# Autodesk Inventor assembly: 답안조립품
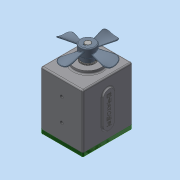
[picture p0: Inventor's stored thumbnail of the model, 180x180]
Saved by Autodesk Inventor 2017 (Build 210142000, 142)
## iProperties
Part Number: 답안조립품
Material: 일반
Document SubType Name: Assembly
Designer: MRC
Mass: 2663.33 g
Surface Area: 1952.92 cm^2
Volume: 798.897 cm^3
Density: 3.33376 g/cm^3
Author: MRC
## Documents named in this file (17)
- C:\Users\MRC\Desktop\610205V1005\답안조립품.iam
- C:\Users\MRC\Desktop\610205V1005\본체.ipt
- C:\Users\MRC\Desktop\610205V1005\가변스프링.ipt
- C:\Users\MRC\Desktop\610205V1005\멈춤나사 M3x8.ipt
- C:\Users\MRC\Desktop\610205V1005\메인 기어 축.ipt
- C:\Users\MRC\Desktop\610205V1005\베어링 608.ipt
- C:\Users\MRC\Desktop\610205V1005\베어링 6903.ipt
- C:\Users\MRC\Desktop\610205V1005\볼트 M4 x 10.ipt
- C:\Users\MRC\Desktop\610205V1005\부시.ipt
- C:\Users\MRC\Desktop\610205V1005\서브 기어 축.ipt
- C:\Users\MRC\Desktop\610205V1005\슬라이더.ipt
- C:\Users\MRC\Desktop\610205V1005\오일 실 8 22 7.ipt
- C:\Users\MRC\Desktop\610205V1005\오일 실 17 30 8.ipt
- C:\Users\MRC\Desktop\610205V1005\커버.ipt
- C:\Users\MRC\Desktop\610205V1005\키 5 x 5 x 24.ipt
- C:\Users\MRC\Desktop\610205V1005\팬날개.ipt
- 팬날개.ipt
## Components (1 placed, 1 different names)
1. 가변스프링:1
